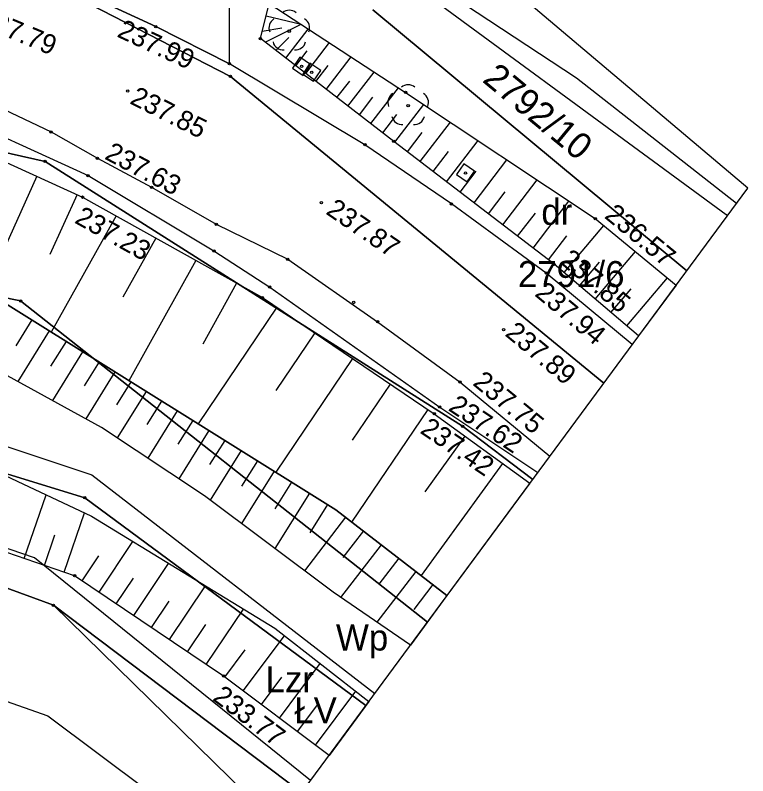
# Model space of a CAD drawing. Extents: x 6596400 to 6597200, y 5539751 to 5540251.
# Drawn here: x 6596805.04 to 6596833.15, y 5540046.04 to 5540075.21 of the extents above; entities that cross this region are included whole.
import ezdxf

# ---------------------------------------------------------------- set-up
doc = ezdxf.new("R2010")
doc.units = 0
for name, color, linetype in [('000 Inne (niezydentyfikowane)', 7, 'Continuous'), ('140-Punkty robocze', 7, 'Continuous'), ('203-punkt graniczny', 7, 'Continuous'), ('209-oznaczenie konturu klasyfikacyjnego', 7, 'Continuous'), ('210-oznaczenie konturu użytku gruntowego', 7, 'Continuous'), ('211-numer działki ewidencyjnej', 7, 'Continuous'), ('217-kontur klasyfikacyjny', 7, 'Continuous'), ('218-kontur użytku gruntowego', 7, 'Continuous'), ('219-działka ewidencyjna', 7, 'Continuous'), ('bariera ochronna', 7, 'Continuous'), ('drzewo liściaste', 7, 'Continuous'), ('jezdnia', 7, 'Continuous'), ('Linia obszaru zagospodarowania terenu', 7, 'Continuous'), ('pikieta sztuczna', 7, 'Continuous'), ('pikieta sztuczna-Atr2', 7, 'Continuous'), ('rów melioracyjny (poligon)', 7, 'Continuous'), ('skarpa nieumocniona', 7, 'Continuous'), ('skarpa umocniona', 7, 'Continuous'), ('Strefa korytarza ekologicznego', 7, 'Continuous'), ('właz do komory lub kanału - kwadratowy', 7, 'Continuous'), ('Zakres', 7, 'Continuous')]:
    doc.layers.add(name, color=color, linetype=linetype)

# ---------------------------------------------------------------- blocks, each defined once
blk = doc.blocks.new('203')
blk.add_circle((0, 0), 0.045)
blk = doc.blocks.new('OP021')
blk.add_circle((0, 0), 0.05)
for centre, start, end in [((0, 0.4), 49.272, 130.728), ((-0.38, 0.124), 121.308, 202.548), ((0.38, 0.124), 337.452, 58.692), ((-0.235, -0.324), 193.221, 274.871), ((0.235, -0.324), 265.129, 346.779)]:
    blk.add_arc(centre, 0.4, start, end)
blk = doc.blocks.new('US22A')
blk.add_lwpolyline([(-0.25, -0.25), (0.25, -0.25), (0.25, 0.25), (-0.25, 0.25)], close=True)
blk = doc.blocks.new('PIKIETA')
blk.add_circle((0, 0), 0.045)
blk = doc.blocks.new('PW01')
blk.add_circle((0, 0), 0.045)

msp = doc.modelspace()

# ---------------------------------------------------------------- linework, layer by layer
at = {"layer": '000 Inne (niezydentyfikowane)'}
for p, q in [((6596814.67, 5540075.18), (6596816.02, 5540074.86)), ((6596814.52, 5540074.6), (6596815.27, 5540074.73)), ((6596814.64, 5540074.17), (6596816.02, 5540074.86)), ((6596815.43, 5540073.56), (6596816.29, 5540074.68)), ((6596815.05, 5540073.85), (6596815.54, 5540074.35)), ((6596816.19, 5540072.97), (6596817.1, 5540074.16)), ((6596815.81, 5540073.27), (6596816.25, 5540073.84)), ((6596816.98, 5540072.36), (6596817.94, 5540073.61)), ((6596816.58, 5540072.67), (6596817.05, 5540073.28)), ((6596817.81, 5540071.72), (6596818.82, 5540073.03)), ((6596817.39, 5540072.05), (6596817.88, 5540072.68)), ((6596818.69, 5540071.05), (6596819.75, 5540072.43)), ((6596818.25, 5540071.39), (6596818.76, 5540072.06)), ((6596819.61, 5540070.34), (6596820.72, 5540071.78)), ((6596819.15, 5540070.7), (6596819.69, 5540071.4)), ((6596820.58, 5540069.6), (6596821.74, 5540071.11)), ((6596820.09, 5540069.97), (6596820.66, 5540070.71)), ((6596821.59, 5540068.82), (6596822.8, 5540070.4)), ((6596821.08, 5540069.21), (6596821.67, 5540069.98)), ((6596822.65, 5540068.01), (6596823.91, 5540069.66)), ((6596822.12, 5540068.42), (6596822.73, 5540069.23)), ((6596805.88, 5540069.03), (6596803.84, 5540064.53)), ((6596823.75, 5540067.17), (6596825.07, 5540068.89)), ((6596807.42, 5540068.33), (6596806.37, 5540066.03)), ((6596823.2, 5540067.59), (6596823.84, 5540068.44)), ((6596824.91, 5540066.28), (6596826.29, 5540068.08)), ((6596808.92, 5540067.51), (6596806.43, 5540063.05)), ((6596824.32, 5540066.73), (6596825, 5540067.61)), ((6596826.1, 5540065.34), (6596827.63, 5540067.14)), ((6596810.44, 5540066.66), (6596809.17, 5540064.4)), ((6596825.5, 5540065.83), (6596826.21, 5540066.75)), ((6596827.3, 5540064.32), (6596828.84, 5540066.14)), ((6596811.98, 5540065.8), (6596809.41, 5540061.19)), ((6596826.69, 5540064.83), (6596827.46, 5540065.74)), ((6596828.51, 5540063.29), (6596830.07, 5540065.13)), ((6596813.54, 5540064.93), (6596812.24, 5540062.59)), ((6596827.9, 5540063.81), (6596828.68, 5540064.72)), ((6596815.08, 5540064.01), (6596812.06, 5540059.54)), ((6596805.68, 5540063.52), (6596805.07, 5540062.53)), ((6596806.35, 5540063.1), (6596805.14, 5540061.16)), ((6596816.54, 5540063.02), (6596815.05, 5540060.81)), ((6596807, 5540062.7), (6596806.4, 5540061.75)), ((6596807.63, 5540062.3), (6596806.47, 5540060.43)), ((6596808.26, 5540061.91), (6596807.69, 5540060.99)), ((6596817.99, 5540062.04), (6596815.04, 5540057.68)), ((6596808.87, 5540061.53), (6596807.75, 5540059.73)), ((6596809.48, 5540061.15), (6596808.93, 5540060.27)), ((6596819.43, 5540061.06), (6596817.97, 5540058.91)), ((6596810.07, 5540060.78), (6596808.96, 5540059)), ((6596810.66, 5540060.41), (6596810.1, 5540059.51)), ((6596811.26, 5540060.04), (6596810.13, 5540058.22)), ((6596820.87, 5540060.09), (6596817.95, 5540055.77)), ((6596811.86, 5540059.66), (6596811.29, 5540058.75)), ((6596812.47, 5540059.28), (6596811.32, 5540057.43)), ((6596822.3, 5540059.06), (6596820.76, 5540056.93)), ((6596813.09, 5540058.9), (6596812.5, 5540057.97)), ((6596813.71, 5540058.51), (6596812.52, 5540056.61)), ((6596814.34, 5540058.12), (6596813.73, 5540057.14)), ((6596823.74, 5540058.02), (6596820.62, 5540053.72)), ((6596814.98, 5540057.72), (6596813.73, 5540055.71)), ((6596815.65, 5540057.3), (6596815, 5540056.27)), ((6596805.39, 5540054.37), (6596806.23, 5540056.81)), ((6596816.33, 5540056.88), (6596815, 5540054.75)), ((6596817.03, 5540056.44), (6596816.35, 5540055.35)), ((6596806.92, 5540053.85), (6596807.7, 5540056.12)), ((6596817.72, 5540055.95), (6596816.14, 5540053.9)), ((6596806.17, 5540054.1), (6596806.57, 5540055.28)), ((6596818.41, 5540055.43), (6596817.62, 5540054.41)), ((6596808.26, 5540053.08), (6596809.56, 5540055.02)), ((6596819.09, 5540054.9), (6596817.53, 5540052.88)), ((6596807.61, 5540053.52), (6596808.25, 5540054.47)), ((6596819.76, 5540054.38), (6596819, 5540053.39)), ((6596809.59, 5540052.18), (6596810.93, 5540054.18)), ((6596820.42, 5540053.87), (6596818.92, 5540051.93)), ((6596808.92, 5540052.63), (6596809.58, 5540053.62)), ((6596810.96, 5540051.26), (6596812.34, 5540053.32)), ((6596821.07, 5540053.37), (6596820.34, 5540052.41)), ((6596810.27, 5540051.73), (6596810.95, 5540052.74)), ((6596812.37, 5540050.31), (6596813.8, 5540052.43)), ((6596811.66, 5540050.79), (6596812.36, 5540051.84)), ((6596813.79, 5540049.29), (6596815.38, 5540051.41)), ((6596813.09, 5540049.82), (6596813.87, 5540050.87)), ((6596815.19, 5540048.25), (6596816.75, 5540050.34)), ((6596814.49, 5540048.77), (6596815.28, 5540049.82)), ((6596816.56, 5540047.21), (6596818.11, 5540049.28)), ((6596815.88, 5540047.73), (6596816.65, 5540048.77))]:
    msp.add_line(p, q, dxfattribs=at)
at = {"layer": '217-kontur klasyfikacyjny'}
for points in [[(6596806.51, 5540052.58), (6596787.06, 5540059.7)], [(6596815.117, 5540044.153), (6596806.51, 5540052.58)], [(6596806.51, 5540052.58), (6596815.117, 5540044.153)], [(6596816.032, 5540045.393), (6596806.51, 5540052.58)]]:
    msp.add_lwpolyline(points, dxfattribs=at)
at = {"layer": '218-kontur użytku gruntowego'}
for points in [[(6596800.73, 5540079.33), (6596813.3, 5540072.86)], [(6596813.3, 5540072.86), (6596800.73, 5540079.33)], [(6596818.76, 5540075.41), (6596830.806, 5540065.405)], [(6596830.806, 5540065.405), (6596818.76, 5540075.41)], [(6596806.19, 5540069.6), (6596785.82, 5540074.19)], [(6596785.82, 5540074.19), (6596806.19, 5540069.6)], [(6596813.3, 5540072.86), (6596827.624, 5540061.094)], [(6596827.624, 5540061.094), (6596813.3, 5540072.86)], [(6596822.21, 5540059.44), (6596806.19, 5540069.6)], [(6596806.19, 5540069.6), (6596822.21, 5540059.44)], [(6596786.16, 5540068.13), (6596805.25, 5540064.25)], [(6596805.25, 5540064.25), (6596786.16, 5540068.13)], [(6596805.25, 5540064.25), (6596820.857, 5540051.929)], [(6596820.857, 5540051.929), (6596805.25, 5540064.25)], [(6596807.71, 5540056.7), (6596786.08, 5540063.35)], [(6596786.08, 5540063.35), (6596807.71, 5540056.7)], [(6596806.51, 5540052.58), (6596787.06, 5540059.7)], [(6596787.06, 5540059.7), (6596806.51, 5540052.58)], [(6596824.899, 5540057.403), (6596822.21, 5540059.44)], [(6596822.21, 5540059.44), (6596824.899, 5540057.403)], [(6596818.497, 5540048.731), (6596807.71, 5540056.7)], [(6596807.71, 5540056.7), (6596818.497, 5540048.731)], [(6596815.117, 5540044.153), (6596806.51, 5540052.58)], [(6596806.51, 5540052.58), (6596815.117, 5540044.153)], [(6596816.032, 5540045.393), (6596806.51, 5540052.58)], [(6596806.51, 5540052.58), (6596816.032, 5540045.393)]]:
    msp.add_lwpolyline(points, dxfattribs=at)
at = {"layer": '219-działka ewidencyjna'}
for points in [[(6596813.3, 5540072.86), (6596800.73, 5540079.33)], [(6596830.806, 5540065.405), (6596818.76, 5540075.41)], [(6596806.19, 5540069.6), (6596785.82, 5540074.19)], [(6596827.624, 5540061.094), (6596813.3, 5540072.86)], [(6596822.21, 5540059.44), (6596806.19, 5540069.6)], [(6596805.25, 5540064.25), (6596786.16, 5540068.13)], [(6596820.857, 5540051.929), (6596805.25, 5540064.25)], [(6596807.71, 5540056.7), (6596786.08, 5540063.35)], [(6596806.51, 5540052.58), (6596787.06, 5540059.7)], [(6596824.899, 5540057.403), (6596822.21, 5540059.44)], [(6596818.497, 5540048.731), (6596807.71, 5540056.7)], [(6596816.032, 5540045.393), (6596806.51, 5540052.58)]]:
    msp.add_lwpolyline(points, dxfattribs=at)
at = {"layer": 'bariera ochronna'}
msp.add_lwpolyline([(6596774.86, 5540078.28), (6596785.35, 5540076.32), (6596790.54, 5540075.22), (6596793.53, 5540074.48), (6596795.64, 5540073.93), (6596798.3, 5540073.09), (6596802.06, 5540071.69), (6596807.84, 5540069.06), (6596812.67, 5540066.17), (6596814.81, 5540064.78), (6596821.33, 5540060.18), (6596825.095, 5540057.67)], dxfattribs=at)
at = {"layer": 'jezdnia'}
for points in [[(6596816.136, 5540099.702), (6596814.5, 5540086.93), (6596812.47, 5540082.2), (6596810.01, 5540078.61), (6596805.94, 5540076.86), (6596810.44, 5540074.77), (6596813.26, 5540073.35), (6596813.26, 5540075.57), (6596813.95, 5540078.37), (6596817.04, 5540086.1), (6596818.162, 5540098.968)], [(6596828.719, 5540062.578), (6596825.42, 5540065.32), (6596821.78, 5540067.97), (6596818.46, 5540070.24), (6596813.26, 5540073.35), (6596810.44, 5540074.77), (6596805.94, 5540076.86), (6596804.14, 5540077.61), (6596801.52, 5540078.62), (6596798.28, 5540079.76), (6596795.16, 5540080.71), (6596792.67, 5540081.35), (6596788.77, 5540082.14), (6596786.6, 5540082.54), (6596777.46, 5540084.34), (6596768.21, 5540086.12), (6596759.17, 5540087.8), (6596749.8, 5540089.83), (6596749.82, 5540090.44), (6596743.18, 5540091.67), (6596739.76, 5540092.34), (6596735.83, 5540093.08), (6596728.26, 5540094.5), (6596723.35, 5540095.14)], [(6596748.72, 5540084.9), (6596758.31, 5540082.61), (6596767.09, 5540080.95), (6596776.43, 5540079.11), (6596785.57, 5540077.35), (6596790.64, 5540076.33), (6596793.76, 5540075.4), (6596796, 5540074.75), (6596799.11, 5540073.89), (6596802.37, 5540072.55), (6596804.34, 5540071.72), (6596806.42, 5540070.73), (6596808.2, 5540069.72), (6596810.28, 5540068.61), (6596812.76, 5540067.19), (6596815.5, 5540065.85), (6596818.95, 5540063.45), (6596822.11, 5540061.14), (6596825.559, 5540058.298)]]:
    msp.add_lwpolyline(points, dxfattribs=at)
at = {"layer": 'Linia obszaru zagospodarowania terenu'}
for points in [[(6596664.616, 5540132.112), (6596671.21, 5540127.95), (6596681.8, 5540121.54), (6596690.35, 5540115.69), (6596701.61, 5540105.97), (6596709.34, 5540098.61), (6596715.39, 5540091.82), (6596718.63, 5540088.53), (6596721.87, 5540084.71), (6596726.1, 5540083.21), (6596730.7, 5540082.79), (6596730.91, 5540075), (6596745.51, 5540074.64), (6596746.77, 5540082.74), (6596765.15, 5540085.09), (6596776.62, 5540086.27), (6596789.34, 5540086.1), (6596798.37, 5540085.54), (6596805.65, 5540083.56), (6596813.11, 5540081.53), (6596819.41, 5540077.54), (6596826.58, 5540072.81), (6596832.721, 5540067.998)], [(6596720.263, 5540058.387), (6596728.96, 5540057.84), (6596731.45, 5540057.76), (6596731.02, 5540064.64), (6596745.49, 5540064.58), (6596746.99, 5540056.99), (6596772.84, 5540062.25), (6596786.21, 5540064.83), (6596807.99, 5540057.58), (6596818.837, 5540049.192)], [(6596816.371, 5540045.853), (6596805.78, 5540054.39), (6596786.09, 5540061.13), (6596752.3, 5540048.46), (6596750.16, 5540045.43), (6596750.4, 5540037.69), (6596745.15, 5540037.73), (6596747.098, 5540030.366)]]:
    msp.add_lwpolyline(points, dxfattribs=at)
at = {"layer": 'rów melioracyjny (poligon)'}
for points in [[(6596820.208, 5540051.05), (6596817.24, 5540053.08), (6596812.31, 5540056.77), (6596808.36, 5540059.4), (6596802.55, 5540062.58), (6596795.13, 5540065.25), (6596788.99, 5540067.23), (6596782.3, 5540068.04), (6596775.52, 5540068.1), (6596768.51, 5540067.33), (6596764.82, 5540065.79), (6596761.35, 5540063.62), (6596758.63, 5540061.34), (6596754.58, 5540058.6), (6596752.07, 5540056.28), (6596746.75, 5540055.19), (6596741.65, 5540054.82), (6596742.01, 5540050.53), (6596747.46, 5540050.98), (6596751.88, 5540051.19), (6596756.01, 5540053.96), (6596757.53, 5540054.97), (6596761.73, 5540059.12)], [(6596761.73, 5540059.12), (6596765.87, 5540062.28), (6596769.5, 5540063.71), (6596775.27, 5540065.15), (6596782.49, 5540064.38), (6596788.18, 5540063.76), (6596793.92, 5540062.6), (6596807.97, 5540055.99), (6596815, 5540051.7), (6596818.611, 5540048.887)]]:
    msp.add_lwpolyline(points, dxfattribs=at)
at = {"layer": 'skarpa nieumocniona'}
msp.add_lwpolyline([(6596820.02, 5540072.25), (6596827.3, 5540067.41), (6596830.4, 5540064.86), (6596828.96, 5540062.91), (6596825.72, 5540065.66), (6596819.57, 5540070.37), (6596814.45, 5540074.31), (6596814.79, 5540075.66)], close=True, dxfattribs=at)
msp.add_lwpolyline([(6596820.02, 5540072.25), (6596827.3, 5540067.41), (6596830.4, 5540064.86), (6596828.96, 5540062.91), (6596825.72, 5540065.66), (6596819.57, 5540070.37), (6596814.45, 5540074.31), (6596814.79, 5540075.66)], close=True, dxfattribs=at)
at = {"layer": 'skarpa umocniona'}
msp.add_lwpolyline([(6596784.99, 5540074.54), (6596793.19, 5540073.11), (6596795.39, 5540072.78), (6596798.65, 5540071.87), (6596801.76, 5540070.9), (6596807.63, 5540068.23), (6596814.53, 5540064.38), (6596821.12, 5540059.92), (6596824.79, 5540057.26), (6596821.61, 5540052.95), (6596817.35, 5540056.24), (6596804.46, 5540064.28), (6596795.61, 5540067.88), (6596788.93, 5540069.36), (6596781.56, 5540070.33)], dxfattribs=at)
msp.add_lwpolyline([(6596784.99, 5540074.54), (6596793.19, 5540073.11), (6596795.39, 5540072.78), (6596798.65, 5540071.87), (6596801.76, 5540070.9), (6596807.63, 5540068.23), (6596814.53, 5540064.38), (6596821.12, 5540059.92), (6596824.79, 5540057.26), (6596821.61, 5540052.95), (6596817.35, 5540056.24), (6596804.46, 5540064.28), (6596795.61, 5540067.88), (6596788.93, 5540069.36), (6596781.56, 5540070.33)], dxfattribs=at)
for points in [[(6596781.29, 5540069.35), (6596788.9, 5540068.52), (6596795.46, 5540066.97), (6596804.46, 5540064.28), (6596817.35, 5540056.24), (6596821.61, 5540052.95), (6596820.21, 5540051.05), (6596817.24, 5540053.08), (6596812.31, 5540056.77), (6596808.36, 5540059.4), (6596802.55, 5540062.58), (6596795.13, 5540065.25), (6596788.99, 5540067.23), (6596782.3, 5540068.04), (6596775.52, 5540068.1), (6596768.51, 5540067.33), (6596764.82, 5540065.79), (6596761.35, 5540063.62), (6596758.63, 5540061.34), (6596756.16, 5540061.25), (6596760.14, 5540064.35), (6596763.69, 5540066.4), (6596768.63, 5540068.26), (6596775.9, 5540069.36)], [(6596781.29, 5540069.35), (6596788.9, 5540068.52), (6596795.46, 5540066.97), (6596804.46, 5540064.28), (6596817.35, 5540056.24), (6596821.61, 5540052.95), (6596820.21, 5540051.05), (6596817.24, 5540053.08), (6596812.31, 5540056.77), (6596808.36, 5540059.4), (6596802.55, 5540062.58), (6596795.13, 5540065.25), (6596788.99, 5540067.23), (6596782.3, 5540068.04), (6596775.52, 5540068.1), (6596768.51, 5540067.33), (6596764.82, 5540065.79), (6596761.35, 5540063.62), (6596758.63, 5540061.34), (6596756.16, 5540061.25), (6596760.14, 5540064.35), (6596763.69, 5540066.4), (6596768.63, 5540068.26), (6596775.9, 5540069.36)], [(6596782.49, 5540064.38), (6596788.18, 5540063.76), (6596793.92, 5540062.6), (6596807.97, 5540055.99), (6596815, 5540051.7), (6596818.61, 5540048.89), (6596817.09, 5540046.82), (6596813.04, 5540049.86), (6596807.32, 5540053.71), (6596801, 5540055.88), (6596793.16, 5540059.3), (6596788.6, 5540060.8), (6596783.73, 5540060.81), (6596779.28, 5540061), (6596774.44, 5540061.86), (6596770.5, 5540060.07), (6596764.63, 5540056.07), (6596761.73, 5540059.12), (6596765.87, 5540062.28), (6596769.5, 5540063.71), (6596775.27, 5540065.15)], [(6596782.49, 5540064.38), (6596788.18, 5540063.76), (6596793.92, 5540062.6), (6596807.97, 5540055.99), (6596815, 5540051.7), (6596818.61, 5540048.89), (6596817.09, 5540046.82), (6596813.04, 5540049.86), (6596807.32, 5540053.71), (6596801, 5540055.88), (6596793.16, 5540059.3), (6596788.6, 5540060.8), (6596783.73, 5540060.81), (6596779.28, 5540061), (6596774.44, 5540061.86), (6596770.5, 5540060.07), (6596764.63, 5540056.07), (6596761.73, 5540059.12), (6596765.87, 5540062.28), (6596769.5, 5540063.71), (6596775.27, 5540065.15)]]:
    msp.add_lwpolyline(points, close=True, dxfattribs=at)
at = {"layer": 'Strefa korytarza ekologicznego'}
msp.add_lwpolyline([(6596816.874, 5540099.435), (6596818.24, 5540077.91), (6596832.32, 5540067.56), (6596832.359, 5540067.509)], dxfattribs=at)
at = {"layer": 'Zakres'}
msp.add_lwpolyline([(6596822.22, 5540097.5), (6596800.39, 5540105.4), (6596755.76, 5540121.45), (6596697.73, 5540120.74), (6596659.35, 5540133.92), (6596647.64, 5540109.28), (6596697.73, 5540077), (6596721.01, 5540057.77), (6596727.72, 5540045.95), (6596731.95, 5540033.61), (6596741.17, 5540031.18), (6596755.59, 5540029.2), (6596757.85, 5540044.22), (6596787.25, 5540055.04), (6596806.3, 5540048.33), (6596813.97, 5540042.6), (6596833.15, 5540068.58), (6596822.3, 5540077.75)], close=True, dxfattribs=at)

# ---------------------------------------------------------------- block references
at = {"layer": '140-Punkty robocze'}
for p in [(6596815.56, 5540074.6), (6596814.45, 5540074.31), (6596813.26, 5540073.35), (6596816.03, 5540073.25), (6596816.42, 5540073.02), (6596820.02, 5540072.25), (6596820.12, 5540071.74), (6596806.42, 5540070.73), (6596819.57, 5540070.37), (6596818.46, 5540070.24), (6596822.32, 5540069.16), (6596807.84, 5540069.06), (6596810.28, 5540068.61), (6596821.78, 5540067.97), (6596812.76, 5540067.19), (6596812.67, 5540066.17), (6596815.5, 5540065.85), (6596814.81, 5540064.78), (6596814.53, 5540064.38), (6596818.03, 5540064.19), (6596818.95, 5540063.45), (6596807.32, 5540053.71)]:
    msp.add_blockref('PIKIETA', p, dxfattribs=at)
at = {"layer": '203-punkt graniczny'}
for p in [(6596813.3, 5540072.86), (6596806.19, 5540069.6), (6596805.25, 5540064.25), (6596822.21, 5540059.44), (6596807.71, 5540056.7), (6596806.51, 5540052.58)]:
    msp.add_blockref('203', p, dxfattribs=at)
at = {"layer": 'drzewo liściaste'}
for p in [(6596815.56, 5540074.6), (6596820.12, 5540071.74)]:
    msp.add_blockref('OP021', p, dxfattribs=at)
at = {"layer": 'pikieta sztuczna'}
for p in [(6596810.44, 5540074.77), (6596809.36, 5540072.3), (6596808.2, 5540069.72), (6596807.63, 5540068.23), (6596816.79, 5540068.02), (6596827.3, 5540067.41), (6596825.72, 5540065.66), (6596825.42, 5540065.32), (6596823.78, 5540063.15), (6596822.11, 5540061.14), (6596821.33, 5540060.18), (6596821.12, 5540059.92), (6596813.04, 5540049.86)]:
    msp.add_blockref('PW01', p, dxfattribs=at)
at = {"layer": 'właz do komory lub kanału - kwadratowy'}
for p, rotation in [((6596816.03, 5540073.25), -124.15200000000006), ((6596816.42, 5540073.02), -123.50699999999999), ((6596822.32, 5540069.16), -124.992)]:
    msp.add_blockref('US22A', p, dxfattribs=dict(at, rotation=rotation))

# ---------------------------------------------------------------- texts
at = {"layer": '209-oznaczenie konturu klasyfikacyjnego'}
msp.add_text('ŁV', height=1, dxfattribs=at).set_placement((6596815.75, 5540048.05))
at = {"layer": '210-oznaczenie konturu użytku gruntowego'}
for s, p in [('dr', (6596825.23, 5540067.17)), ('Wp', (6596817.35, 5540050.84)), ('Lzr', (6596814.65, 5540049.24))]:
    msp.add_text(s, height=1, dxfattribs=at).set_placement(p)
at = {"layer": '211-numer działki ewidencyjnej'}
msp.add_text('2792/10', height=1, rotation=320.286, dxfattribs=at).set_placement((6596822.931, 5540072.681))
msp.add_text('2791/6', height=1, dxfattribs=at).set_placement((6596824.33, 5540064.78))
at = {"layer": 'pikieta sztuczna-Atr2'}
for s, rotation, p in [('237.79', 337.38, (6596803.602, 5540074.838)), ('237.99', 335.088, (6596808.914, 5540074.4)), ('237.85', 333.273, (6596809.403, 5540071.84)), ('237.63', 331.913, (6596808.437, 5540069.718)), ('237.87', 325.638, (6596816.927, 5540067.611)), ('237.23', 330.84, (6596807.285, 5540067.265)), ('236.57', 320.56, (6596827.614, 5540067.461)), ('237.85', 319.677, (6596825.905, 5540065.728)), ('237.94', 320.268, (6596824.941, 5540064.473)), ('237.89', 320.268, (6596823.801, 5540062.943)), ('237.75', 320.511, (6596822.563, 5540061.051)), ('237.62', 326.31, (6596821.624, 5540060.076)), ('237.42', 325.911, (6596820.54, 5540059.209)), ('233.77', 323.107, (6596812.58, 5540048.96))]:
    msp.add_text(s, height=0.75, rotation=rotation, dxfattribs=at).set_placement(p)

doc.saveas('drawing.dxf')
